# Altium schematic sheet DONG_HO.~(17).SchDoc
size A
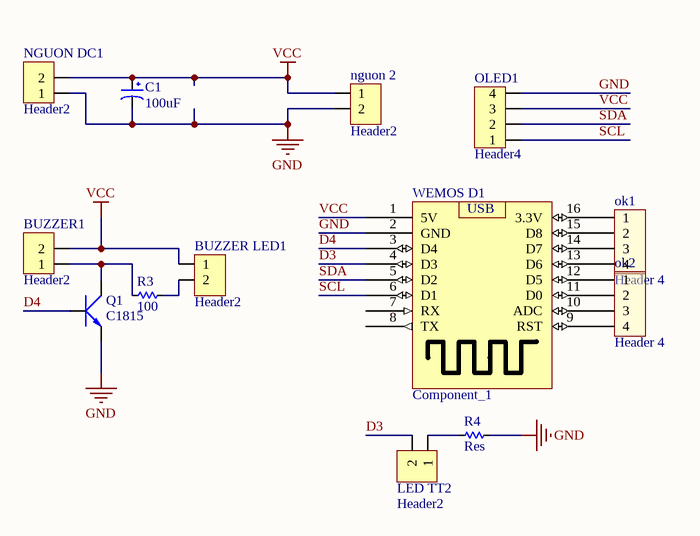
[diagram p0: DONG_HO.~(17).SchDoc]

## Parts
BUZZER1  Header2  [Header2]
BUZZER_LED1  Header2  [Header2]
C1  100uF  [CP1/2.5]
LED_TT2  Header2  [Header2]
nguon_2  Header2  [Header2]
NGUON_DC1  Header2  [Header2]
ok1  Header 4  [HED4]
ok2  Header 4  [HED4]
OLED1  Header4  [Header4]
Q1  C1815  [QTO-92]
R3  100  [RES-1/8W-SMALL]
R4  Res  [RES-1/8W-SMALL]
WEMOS_D1  Component_1  [ESP WEMOS MINI]

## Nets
GND: C1.2 nguon_2.2 NGUON_DC1.1 OLED1.4 Q1.1(E) R4.2 WEMOS_D1.2(GND)
VCC: BUZZER1.2 BUZZER_LED1.1 C1.1 nguon_2.1 NGUON_DC1.2 OLED1.3 WEMOS_D1.1(5V)
D3: LED_TT2.2 WEMOS_D1.4(D3)
D4: Q1.3(B) WEMOS_D1.3(D4)
SCL: OLED1.1 WEMOS_D1.6(D1)
SDA: OLED1.2 WEMOS_D1.5(D2)
NetBUZZER1_1: BUZZER1.1 Q1.2(C) R3.1
NetBUZZER_LED1_2: BUZZER_LED1.2 R3.2
NetLED_TT2_1: LED_TT2.1 R4.1
Netok1_1: ok1.1 WEMOS_D1.16(3.3V)
Netok1_2: ok1.2 WEMOS_D1.15(D8)
Netok1_3: ok1.3 WEMOS_D1.14(D7)
Netok1_4: ok1.4 WEMOS_D1.13(D6)
Netok2_1: ok2.1 WEMOS_D1.12(D5)
Netok2_2: ok2.2 WEMOS_D1.11(D0)
Netok2_3: ok2.3 WEMOS_D1.10(ADC)
Netok2_4: ok2.4 WEMOS_D1.9(RST)

Not connected (* = marked no-connect by the designer): WEMOS_D1 7(RX) 8(TX)

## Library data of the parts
BUZZER1 BUZZER_LED1 LED_TT2 nguon_2 NGUON_DC1 = Header2: Header IDC, 2 x 1 Pin Vertical 2.54mm Pitch (Non-Boxed, Male); Manufacturer: W¨¹rth Elektronik eiSos GmbH; partNo: 613002143121; ComponentLink1 Description: Manufacturer; ComponentLink2 Description: Datasheet; NoPins: 02
C1 = CP2: C 47uF/50V , 220uF/16V; Value: 47uF/16 - 50V; Description 1: 470uF/6,3V - 330uF/10V - 220uF/16V; Description 2: 100uF/25V - 35V - 47uF/50V - 22uF/100V; Description 3: 33uF => 47uF/63V - 1uF => 4,7uF/160V; Description 4: 1uF => 2,2uF/250V - 1uF/350V
ok1 ok2 = Hed4: Header 4 (Green)
OLED1 = Header4: Header IDC, 4 x 1 Pin Vertical 2.54mm Pitch (Non-Boxed, Male); Manufacturer: W¨¹rth Elektronik eiSos GmbH; partNo: 613002143121; ComponentLink1 Description: Manufacturer; ComponentLink2 Description: Datasheet; NoPins: 02
Q1 = C1815: NPN 600mW, ECB
R3 R4 = Res: Manufacturer: Generic Components; Class: Passive; SubClass: R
